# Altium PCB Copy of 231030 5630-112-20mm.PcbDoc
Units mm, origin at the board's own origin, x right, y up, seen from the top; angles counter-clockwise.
Board outline 112 x 20 mm, 2 copper layers (Top Layer, Bottom Layer); 11 components, 6 nets, 34 pads, 136 vias.
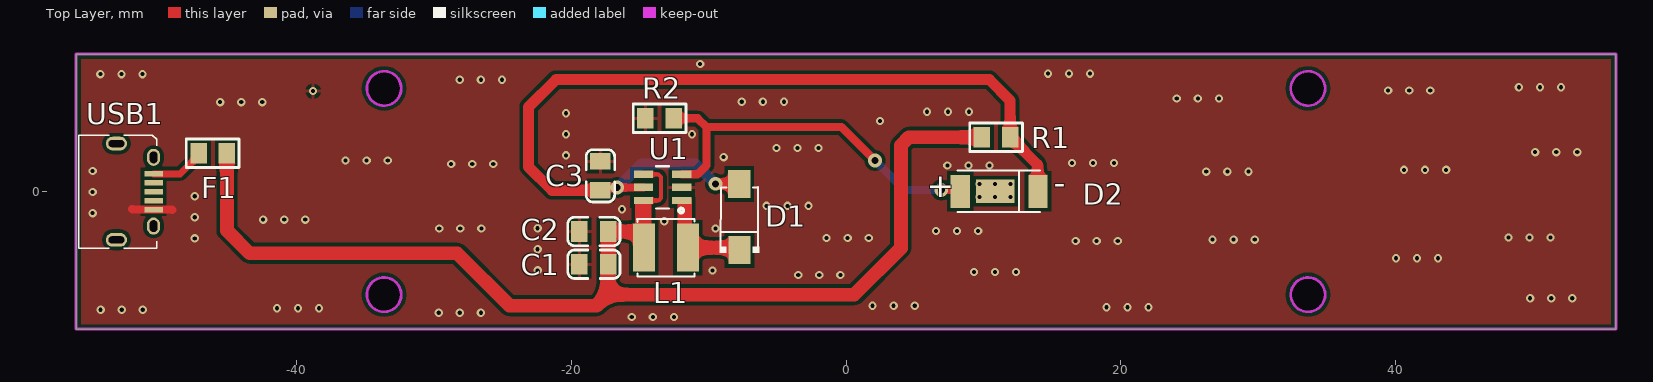
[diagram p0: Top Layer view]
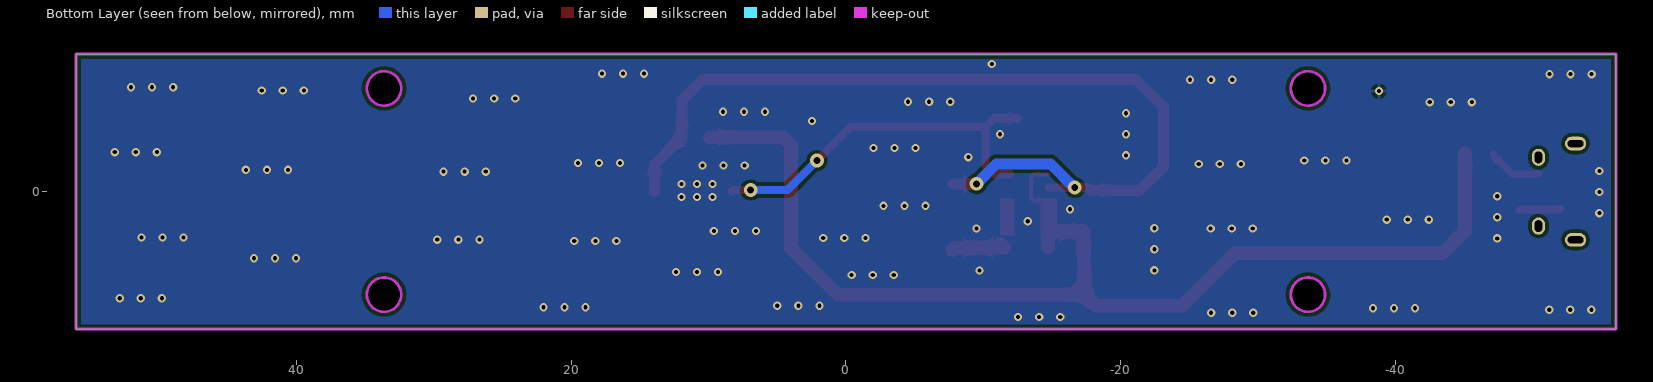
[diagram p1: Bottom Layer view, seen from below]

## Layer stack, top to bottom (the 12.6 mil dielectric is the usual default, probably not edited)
Top Solder: solder mask 0.0102, Solder Resist, Dk 3.5
Top Layer: signal copper 0.0356
Dielectric 1: dielectric 0.32, FR-4, Dk 4.8
Bottom Layer: signal copper 0.0356
Bottom Solder: solder mask 0.0102, Solder Resist, Dk 3.5

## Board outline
-56,-10 56,-10 56,10 -56,10
cut-out: -33.6,6.25 cw(c-33.6,7.5) -34.85,7.5 cw(c-33.6,7.5) -33.6,8.75 cw(c-33.6,7.5) -32.35,7.5 cw(c-33.6,7.5)
cut-out: -33.6,-8.75 cw(c-33.6,-7.5) -34.85,-7.5 cw(c-33.6,-7.5) -33.6,-6.25 cw(c-33.6,-7.5) -32.35,-7.5 cw(c-33.6,-7.5)
cut-out: 33.6,6.25 cw(c33.6,7.5) 32.35,7.5 cw(c33.6,7.5) 33.6,8.75 cw(c33.6,7.5) 34.85,7.5 cw(c33.6,7.5)
cut-out: 33.6,-8.75 cw(c33.6,-7.5) 32.35,-7.5 cw(c33.6,-7.5) 33.6,-6.25 cw(c33.6,-7.5) 34.85,-7.5 cw(c33.6,-7.5)

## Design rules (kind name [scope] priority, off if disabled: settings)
Clearance Clearance_1 [All] p1: gap=0.254 ignorepadtopadclearanceinfootprint=FALSE
Clearance [OnLayer('Top Layer') vs InPolygon] p2: gap=0.305 ignorepadtopadclearanceinfootprint=FALSE
ComponentClearance [All] p1: gap=0 collisioncheckmode=3 verticalgap=0 showdistances=FALSE
MinimumSolderMaskSliver [All] p1: minsoldermaskwidth=0
PolygonConnect [All] p1: connectstyle=Relief reliefconductorwidth=0.254 reliefentries=4 polygonreliefangle="90 Angle" airgapwidth=0.254
RoutingVias [All] p1: holewidth=0.711 width=1.27 viastyle="Through Hole" minholewidth=0.711 minwidth=1.27 maxholewidth=0.711 maxwidth=1.27
SilkToSilkClearance [All] p1: silktosilkclearance=0
SilkToSolderMaskClearance [IsPad] p1: minsilkscreentomaskgap=0 clearancetoexposedcopper=TRUE
SolderMaskExpansion [All] p1: expansion=0.102 istentingtop=FALSE
Width [All] p1: maxlimit=2 minlimit=0.254 preferedwidth=0.254 minimp=50.000000 maximp=50.000000 favimp=50.000000
26 further rules are at their usual default settings.

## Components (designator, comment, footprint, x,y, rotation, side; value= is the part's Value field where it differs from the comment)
C1 "22uF/10V" 0805-C -18.284,-5.304 r180 top
C2 "10uF/10V" 0805-C -18.386,-2.891 r0 top value=100pF
C3 "10uF/10V" 0805-C -17.848,1.194 r270 top value=100pF
D1 "SS14" SMA(DO-214AC) -7.759,-1.853 r90 top
D2 "XL-5730UWC-05" LED-SMD_3P-L5.7-W3.0-RD 10.838,0.021 r180 top
F1 "BSMD0805-050-24V" 0805-L -46.124,2.648 r180 top
L1 "SWPA4030S100MT" IND-SMD_L4.0-W4.0 -13.099,-4.078 r0 top value=10uH
R1 "NC" 0805-L 10.983,4.099 r0 top value=1K
R2 "Res1" 0805-L -13.49,5.469 r0 top value=1K
U1 "MT9284-28J" SOT-23-6 -11.943,-0.646 r180 top
USB1 "10118194-0001LF" MICRO-USB-SMD -53.192,-0.321 r270 top

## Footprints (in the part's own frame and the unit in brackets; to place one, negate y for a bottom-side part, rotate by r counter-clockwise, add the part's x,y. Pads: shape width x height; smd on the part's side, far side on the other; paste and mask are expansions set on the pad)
0805-C [mm]
  rect 1.2x1.5 smd: 1(-1,-0.016) 2(1.1,-0.016)
  silkscreen extent -1.85,-1.05 1.96,1.02, body extent -0.96,-0.64 1.04,0.61, height 0.77
0805-L [mm]
  rect 1.2x1.5 smd: 1(-1.1,-0.143) 2(0.95,-0.143)
  silkscreen extent -1.98,-1.18 1.85,0.89, body extent -1.1,-0.78 0.95,0.49, height 0.6
IND-SMD_L4.0-W4.0 [mm]
  rect 1.6x3.5 smd: 1(-1.6,0) 2(1.6,0)
  silkscreen extent -2.08,-2.1 2.08,2.1
LED-SMD_3P-L5.7-W3.0-RD [mm]
  rect 2.8x1.7 smd: 0(0,0)
  rect 1.4x2.4 smd: 1(-3.12,0) 2(2.52,0)
  silkscreen extent -3.26,-1.5 2.74,1.5
MICRO-USB-SMD [mm]
  rect 0.4x1.35 smd paste-100 mask+0.051: 1(-1.611,2.827) 2(-0.96,2.827) 3(-0.31,2.827) 4(0.34,2.827) 5(0.99,2.827)
  oval 1x1.55 hole 0.5 slot 1.15 at 90 deg: 6(-3.81,0.127) 6(3.19,0.127)
  oval 1.25x0.95 hole 0.55 slot 0.85 at 0 deg: 6(-2.81,2.827) 6(2.19,2.827)
  silkscreen extent -4.41,-2.62 3.79,3.08
SMA(DO-214AC) [mm]
  rect 2.046x1.62 smd: 1(-2.404,-0.009) 2(2.404,0.009)
  silkscreen extent -2.61,-1.44 2.16,1.44
SOT-23-6 [mm] "LED驱动-LM3519"
  rect 1.4x0.533 smd: 1(0,0) 2(0,-0.95) 3(0,-1.9) 4(2.794,-1.9) 5(2.794,-0.95) 6(2.794,0)
  silkscreen extent -0.1,-2.49 1.86,0.89, body extent -0.03,-2.49 2.82,0.59, height 0.99

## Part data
C1: library part Cap, "贴片电容"
C2 C3: library part Cap, "Capacitor"
D1: library part Diode, "Default Diode"
D2: library part LED1, "LED-绿"
F1: library part "Fuse 1"
L1: library part Inductor
R1: library part Res1, "Resistor"
R2: "Resistor"

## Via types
v1: diameter 0.6, hole 0.3, Top Layer to Bottom Layer, tented both sides, 132 vias
v2: diameter 1, hole 0.5, Top Layer to Bottom Layer, tented both sides, 4 vias

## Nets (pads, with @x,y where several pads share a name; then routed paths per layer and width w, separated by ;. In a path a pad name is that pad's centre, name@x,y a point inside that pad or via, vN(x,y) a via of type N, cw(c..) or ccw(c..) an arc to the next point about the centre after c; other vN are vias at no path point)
+5: C1.1 C2.2 F1.1 L1.1 R1.1 U1.4 U1.6 | length 84.9
  Top Layer w0.3: U1.6 -14.732,-0.651 -13.62,-0.651 -13.444,-0.475 -13.444,1.061 -13.637,1.254 U1.4
  Top Layer w1: F1.1 -45.024,-2.833 -43.364,-4.493 -28.276,-4.493 -24.469,-8.3 -18.142,-8.3 -17.34,-7.498 ; C2.2 C2.2@-17.186,-2.807 ; L1.1@-14.661,-4.04 L1.1 -14.699,-3.207 -14.999,-2.907 -17.284,-2.907 C1.1 -17.34,-5.344 -17.34,-7.498 ; R1.1 4.579,3.956 3.993,3.37 3.993,-4.107 0.602,-7.498 -17.34,-7.498
GND: C1.2 C2.1 C3.1 D2.0 R2.1 U1.2 USB1.5 | length 3
  Top Layer w0.6: -51.941,-1.274 -51.904,-1.311 USB1.5 -49.029,-1.311 -49.001,-1.339
  other v1: -15.58,-9.116 -14.048,-9.116 -12.517,-9.116 -29.623,-8.814 -28.091,-8.814 -26.56,-8.814 -54.213,-8.597 -52.681,-8.597 -51.15,-8.597 -41.393,-8.488 -39.862,-8.488 -38.33,-8.488 18.945,-8.417 20.476,-8.417 22.008,-8.417 1.934,-8.309 3.465,-8.309 4.997,-8.309 49.763,-7.757 51.294,-7.757 52.826,-7.757 -3.474,-6.071 -1.943,-6.071 -0.411,-6.071 9.311,-5.843 10.843,-5.843 12.374,-5.843 -9.708,-5.745 -22.427,-5.731 39.996,-4.853 41.527,-4.853 43.059,-4.853 -22.427,-4.199 16.702,-3.599 18.233,-3.599 19.765,-3.599 26.666,-3.5 28.198,-3.5 29.729,-3.5 -47.369,-3.403 -1.411,-3.379 0.12,-3.379 1.652,-3.379 48.179,-3.335 49.71,-3.335 51.242,-3.335 6.551,-2.874 8.083,-2.874 9.614,-2.874 -29.586,-2.694 -28.055,-2.694 -26.523,-2.694 -9.493,-2.694 -22.427,-2.668 -13.221,-2.162 -42.392,-2.042 -40.86,-2.042 -39.329,-2.042 -47.369,-1.871 -54.793,-1.571 -16.294,-1.285 -5.788,-1.04 -4.257,-1.04 -2.725,-1.04 9.718,-0.404 10.843,-0.404 11.967,-0.404 -47.369,-0.34 -54.793,-0.039 9.718,0.551 10.843,0.551 11.967,0.551 26.204,1.449 27.735,1.449 29.267,1.449 -54.793,1.492 40.59,1.581 42.121,1.581 43.653,1.581 7.37,1.905 8.902,1.905 10.433,1.905 -28.717,2.014 -27.186,2.014 -25.654,2.014 16.438,2.076 17.969,2.076 19.501,2.076 -36.395,2.268 -34.863,2.268 -33.332,2.268 -8.898,2.504 -20.366,2.633 50.126,2.868 51.657,2.868 53.189,2.868 -5.059,3.161 -3.528,3.161 -1.996,3.161 -20.366,4.165 -11.209,4.165 2.48,5.126 -20.366,5.696 5.884,5.805 7.415,5.805 8.947,5.805 -45.521,6.505 -43.99,6.505 -42.458,6.505 -7.58,6.536 -6.048,6.536 -4.517,6.536 24.06,6.761 25.591,6.761 27.123,6.761 -38.762,7.306 39.435,7.355 40.966,7.355 42.498,7.355 48.938,7.586 50.47,7.586 52.001,7.586 -28.091,8.134 -26.56,8.134 -25.028,8.134 -54.235,8.541 -52.703,8.541 -51.172,8.541 14.689,8.576 16.22,8.576 17.752,8.576 -10.609,9.276
NetC3_2: C3.2 D1.2 D2.1 R1.2 U1.5 | length 67.7
  Top Layer w0.6: C3.2 -17.654,0.304 -16.642,0.304 U1.5 ; v2(-9.493,0.563) v2@-9.481,0.551
  Top Layer w0.8: C3.2 -21.386,0.094 -23.084,1.792 -23.084,6.158 -21.108,8.134 10.433,8.134 11.933,6.634 R1.2 11.933,3.806 12.133,3.606 12.283,3.606 13.937,1.952 13.937,0.042 D2.1 ; v2@-9.481,0.551 D1.2
  Bottom Layer w0.8: v2(-16.642,0.299) -16.588,0.299 -14.864,2.023 -10.953,2.023 v2(-9.493,0.563)
NetD1_1: D1.1 L1.2 U1.1 | length 4.2
  Top Layer w1: L1.2@-11.209,-3.787 L1.2 -7.929,-4.078 D1.1
NetD2_2: D2.2 R2.2 U1.3 | length 27.9
  Top Layer w0.6: R2.2 -10.785,5.326 -10.151,4.692 ; U1.3 -10.802,1.254 -10.151,1.905 -10.151,4.692 ; v2(2.102,2.263) -0.327,4.692 -10.151,4.692 ; v2(6.935,0.111) 8.228,0.111 D2.2
  Bottom Layer w0.6: v2(2.102,2.263) 4.254,0.111 v2(6.935,0.111)
VUSB: F1.2 USB1.1 | length 4
  Top Layer w0.5: USB1.1 -48.425,1.29 -47.074,2.641 F1.2
pads on no net: USB1.2 USB1.3 USB1.4 USB1.6

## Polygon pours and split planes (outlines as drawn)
GND on Bottom Layer "GND_L02_P000" (solid, remove dead copper, pour order 0): -55.826,10.007 55.628,10.007 55.818,9.817 55.818,-9.837 -56.016,-9.837
GND on Top Layer "GND_L01_P001" (solid, remove dead copper, pour order 1): -55.826,10.043 55.628,10.043 55.818,9.853 55.818,-9.801 -56.016,-9.801

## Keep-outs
Keep-Out Layer:
  circle w0.2: c-33.6,7.5 r1.25
  circle w0.2: c-33.6,-7.5 r1.25
  circle w0.2: c33.6,7.5 r1.25
  circle w0.2: c33.6,-7.5 r1.25
  lines w0.2: -56,-10 -56,10 56,10 56,-10 -56,-10

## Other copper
Top Layer:
  rectangle net NetD1_1: -12.25,-3.207 -11.209,-0.501
  rectangle net +5: -15.329,-3.316 -14.148,-0.479

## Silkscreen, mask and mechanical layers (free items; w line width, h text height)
Top Overlay:
  text "-" at 15.107,-0.787 h3
  text "+" at 5.873,-0.988 h3
Mechanical 1:
  circle w0.2: c33.598,-7.499 r1.244
  circle w0.2: c33.597,7.499 r1.249
  circle w0.2: c-33.599,-7.51 r1.251
  circle w0.2: c-33.591,7.499 r1.258
  lines w0.152: -56.004,9.991 -56,9.987 -56,-9.99 -55.996,-9.994 55.992,-9.994 55.993,-9.995 55.993,9.988 55.996,9.991 -56.004,9.991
